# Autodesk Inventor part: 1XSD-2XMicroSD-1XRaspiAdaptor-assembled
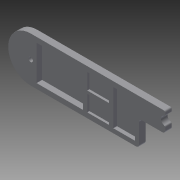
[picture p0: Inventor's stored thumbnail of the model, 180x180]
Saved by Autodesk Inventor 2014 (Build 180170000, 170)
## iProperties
Created: 2015-01
Part Number: 1XSD-2XMicroSD-1XRaspiAdaptor-assembled
Material: Generic
Document SubType Name: Modeling
Designer: Drano
Density: 1 g/cm^3
Appearance: Default
Author: Drano
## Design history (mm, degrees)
derived "raspi adaptor.iam"
thicken "Thicken1" dims "d1" = 1.3, "d2" = 1.3
thicken "Thicken2" dims "d3" = 1, "d4" = 1
thicken "Thicken3" dims "d5" = 1, "d6" = 1
body "Solid1"
node "backplate.ipt:1" dims "d0" = 10
node "1XSD-2XMicroSD-1XRaspiAdaptor.ipt:1" dims "d0" = 10
node "raspi adaptor.iam_Bodies" dims "d0" = 10
